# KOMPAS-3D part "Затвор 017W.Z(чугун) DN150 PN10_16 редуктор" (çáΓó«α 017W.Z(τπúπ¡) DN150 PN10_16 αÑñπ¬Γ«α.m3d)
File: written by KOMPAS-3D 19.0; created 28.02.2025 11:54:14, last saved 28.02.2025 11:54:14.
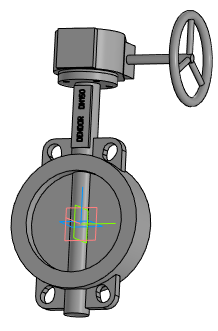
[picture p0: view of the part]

Document properties: Автор: Евгений; Полное имя файла: Затвор 017W.Z(чугун) DN150 PN10_16 редуктор.a3d

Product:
- Part/product: Затвор 017W.Z(чугун) DN150 PN10_16 редуктор
    Масса: 17.303

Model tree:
1. Операция без истории:1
